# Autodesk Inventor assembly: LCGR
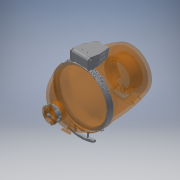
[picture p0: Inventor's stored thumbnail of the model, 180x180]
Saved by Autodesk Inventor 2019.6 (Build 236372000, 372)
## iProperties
Company: none
Created: 2025-09
Part Number: LCGR
Description: CATIA V5 STEP Exchange
Document SubType Name: Assembly
Designer: MMAK
Authority: none
Title: C:\Users\MMAK\Documents\SmarTeam\WEBSITE CAD\LCG\LCGR.stp
Author: none
Revision Number: A
Sending System: CATIA V5 STEP AP203 v2
Preprocessor: CATIA Unofficial Packaging Version SP2
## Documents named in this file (3)
- C:\Users\MMAK\Documents\SmarTeam\WEBSITE CAD\LCG\LCGR.iam
- C:\Users\MMAK\Documents\SmarTeam\WEBSITE CAD\LCG\Block 05.ipt
- C:\Users\MMAK\Documents\SmarTeam\WEBSITE CAD\LCG\Document.ipt
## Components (2 placed, 2 different names)
1. Block 05
2. Document_1.1
